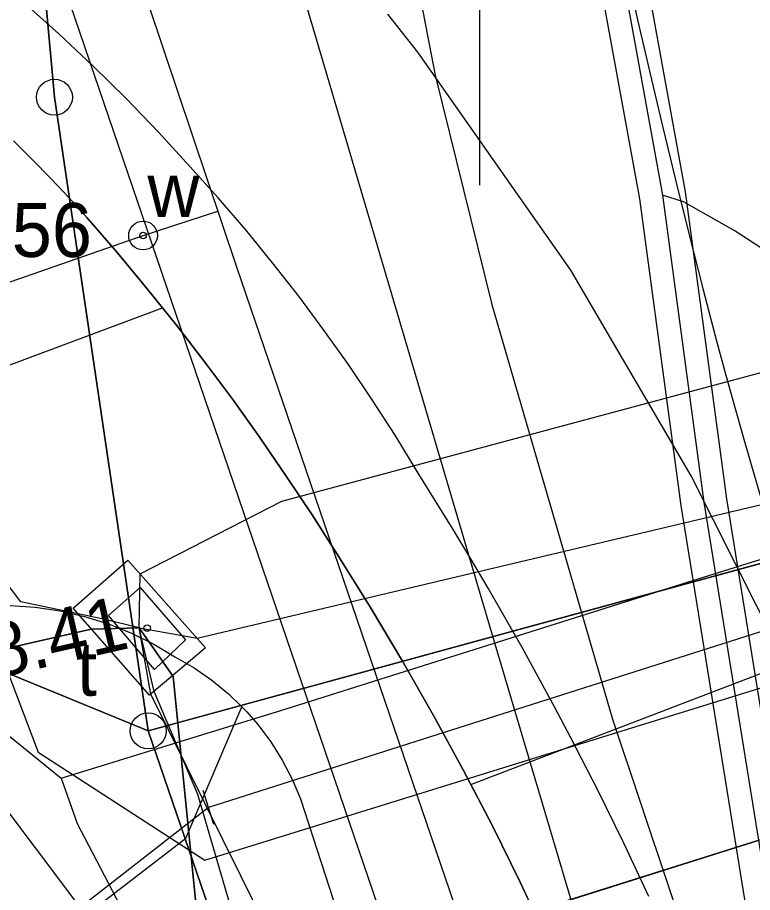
# Model space of a CAD drawing. Extents: x 6432121 to 6432331, y 5662538 to 5662686.
# Drawn here: x 6432243.57 to 6432253.79, y 5662637.67 to 5662649.83 of the extents above; entities that cross this region are included whole.
import ezdxf

# ---------------------------------------------------------------- set-up
doc = ezdxf.new("R2010")
doc.units = 0
for name, color, linetype in [('Warstwa 1', 7, 'Continuous'), ('Warstwa 10', 7, 'Continuous'), ('Warstwa 11', 7, 'Continuous'), ('Warstwa 12', 7, 'Continuous'), ('Warstwa 14', 7, 'Continuous'), ('Warstwa 15', 7, 'Continuous'), ('Warstwa 20', 7, 'Continuous'), ('Warstwa 37', 7, 'Continuous'), ('Warstwa 4', 7, 'Continuous'), ('Warstwa 5', 7, 'Continuous'), ('Warstwa 6', 7, 'Continuous'), ('Warstwa 61', 7, 'Continuous'), ('Warstwa 63', 7, 'Continuous'), ('Warstwa 8', 7, 'Continuous'), ('Warstwa 9', 7, 'Continuous')]:
    doc.layers.add(name, color=color, linetype=linetype)

msp = doc.modelspace()

# ---------------------------------------------------------------- linework, layer by layer
at = {"layer": 'Warstwa 1'}
for p, q in [((6432241.262, 5662679.658), (6432244.087, 5662648.722)), ((6432241.262, 5662679.658), (6432244.087, 5662648.722)), ((6432244.087, 5662648.722), (6432245.39, 5662639.916)), ((6432244.087, 5662648.722), (6432245.39, 5662639.916)), ((6432245.39, 5662639.916), (6432266.742, 5662645.747)), ((6432245.39, 5662639.916), (6432266.742, 5662645.747)), ((6432234.842, 5662644.244), (6432245.39, 5662639.916)), ((6432234.842, 5662644.244), (6432245.39, 5662639.916)), ((6432246.69, 5662636.13), (6432267.75, 5662642.76)), ((6432246.69, 5662636.13), (6432267.75, 5662642.76)), ((6432245.39, 5662639.916), (6432246.69, 5662636.13)), ((6432245.39, 5662639.916), (6432246.69, 5662636.13))]:
    msp.add_line(p, q, dxfattribs=at)
at = {"layer": 'Warstwa 10'}
for points in [[(6432272.61, 5662647.24), (6432246.23, 5662638.85)], [(6432246.23, 5662638.85), (6432244.48, 5662637.49), (6432244.8, 5662632.18)]]:
    msp.add_lwpolyline(points, dxfattribs=at)
for centre in [(6432244.087, 5662648.722), (6432245.39, 5662639.916)]:
    msp.add_circle(centre, 0.25, dxfattribs=at)
at = {"layer": 'Warstwa 11'}
msp.add_lwpolyline([(6432245.11, 5662642.29), (6432246.19, 5662641.07), (6432245.41, 5662640.41), (6432244.35, 5662641.62)], close=True, dxfattribs=at)
at = {"layer": 'Warstwa 12'}
for points in [[(6432260.149, 5662593.584), (6432259.505, 5662597.442), (6432258.113, 5662602.229), (6432246.261, 5662635.045), (6432242.6, 5662639.91), (6432237.105, 5662644.467), (6432235.235, 5662651.91), (6432228.3, 5662671.335), (6432227.148, 5662676.149), (6432227.614, 5662677.443), (6432228.191, 5662677.996), (6432231.551, 5662678.816), (6432233.235, 5662681.053)], [(6432245.267, 5662641.347), (6432245.28, 5662642.1), (6432247.25, 5662643.11), (6432265.86, 5662648.1), (6432266.37, 5662648.378), (6432266.59, 5662649.17), (6432271.25, 5662654.27), (6432275.48, 5662659.44), (6432277.44, 5662662.33), (6432277.171, 5662662.956), (6432277.15, 5662663.67), (6432276.74, 5662675.57), (6432276.54, 5662676.118), (6432276.69, 5662676.8), (6432276.108, 5662681.053)], [(6432245.267, 5662641.347), (6432245.28, 5662642.1), (6432247.25, 5662643.11), (6432265.86, 5662648.1), (6432266.37, 5662648.378), (6432266.59, 5662649.17), (6432271.25, 5662654.27), (6432275.48, 5662659.44), (6432277.44, 5662662.33), (6432277.171, 5662662.956), (6432276.74, 5662675.57), (6432276.54, 5662676.118), (6432276.69, 5662676.8), (6432276.108, 5662681.053)], [(6432251.161, 5662678.636), (6432251.195, 5662678.505), (6432250.722, 5662667.538), (6432250.449, 5662664.161), (6432250.95, 5662660.785), (6432251.946, 5662652.429), (6432252.859, 5662647.409), (6432253.435, 5662643.141), (6432255.033, 5662633.254), (6432255.483, 5662630.016), (6432258.492, 5662620.223), (6432259.57, 5662616.642), (6432259.85, 5662615.749), (6432260.538, 5662613.47), (6432262.28, 5662607.688), (6432262.524, 5662606.965), (6432264.736, 5662599.765)], [(6432264.124, 5662599.577), (6432261.914, 5662606.769), (6432261.67, 5662607.494), (6432259.926, 5662613.286), (6432259.238, 5662615.561), (6432258.958, 5662616.454), (6432257.88, 5662620.037), (6432254.857, 5662629.878), (6432254.401, 5662633.158), (6432252.801, 5662643.047), (6432252.227, 5662647.309), (6432251.312, 5662652.333), (6432250.316, 5662660.701), (6432249.805, 5662664.139), (6432250.084, 5662667.578), (6432250.551, 5662678.439), (6432250.541, 5662678.478)], [(6432244.451, 5662661.055), (6432244.51, 5662660.562), (6432244.747, 5662659.597), (6432247.148, 5662651.498), (6432250.159, 5662641.297), (6432254.564, 5662626.481), (6432257.548, 5662616.394), (6432260.807, 5662605.248), (6432262.453, 5662599.664), (6432266.272, 5662586.802), (6432268.265, 5662580.011), (6432268.423, 5662579.446)], [(6432243.958, 5662654.289), (6432246.621, 5662646.365), (6432250.032, 5662636.381), (6432251.998, 5662630.56), (6432253.864, 5662624.956), (6432256.122, 5662618.174), (6432258.071, 5662612.417), (6432261.076, 5662603.597), (6432261.907, 5662601.278), (6432263.382, 5662596.576), (6432264.52, 5662593.503), (6432265.328, 5662591.162), (6432268.156, 5662582.752), (6432268.733, 5662580.715)], [(6432243.16, 5662653.357), (6432252.465, 5662626.114), (6432254.893, 5662619.007), (6432257.883, 5662610.233), (6432261.03, 5662600.869), (6432263.754, 5662592.896), (6432267.107, 5662583.22), (6432267.857, 5662579.356), (6432269.061, 5662572.854)], [(6432246.73, 5662630.84), (6432246.66, 5662631.45), (6432245.74, 5662640.67), (6432245.267, 5662641.347), (6432244.6, 5662641.33), (6432196.62, 5662630.41), (6432162.36, 5662620.4), (6432161.76, 5662619.96), (6432161.08, 5662620.39), (6432144.64, 5662638.75), (6432139.05, 5662643.99), (6432134.66, 5662649.12), (6432133.76, 5662650.98), (6432133.196, 5662651.358)], [(6432245.267, 5662641.347), (6432244.77, 5662641.47), (6432244.417, 5662641.544), (6432243.62, 5662641.71), (6432240.1, 5662646.34), (6432237.97, 5662649.17), (6432237.33, 5662649.04), (6432237.05, 5662648.95)], [(6432178.74, 5662628.37), (6432200.37, 5662634.75), (6432206.97, 5662636.63), (6432221.29, 5662640.54), (6432232.17, 5662643.77), (6432238.49, 5662646.33), (6432240.86, 5662647.51), (6432243.86, 5662639.62), (6432246.18, 5662638.12), (6432265.49, 5662644.1), (6432264.97, 5662645.92)], [(6432261.405, 5662641.742), (6432260.919, 5662642.019), (6432257.433, 5662644.338), (6432253.539, 5662646.868), (6432252.834, 5662647.268), (6432252.543, 5662647.359)], [(6432157.15, 5662630.3), (6432157.97, 5662630.56), (6432158.44, 5662630.26), (6432165.06, 5662623.42), (6432193.45, 5662632.27), (6432200.21, 5662630.55), (6432202.99, 5662631.34), (6432212.51, 5662634.26), (6432214.29, 5662637.14), (6432238.97, 5662644.59), (6432245.32, 5662646.8), (6432246.36, 5662647.14)], [(6432272.61, 5662647.24), (6432246.23, 5662638.85)], [(6432245.267, 5662641.347), (6432246.071, 5662641.204), (6432265.703, 5662645.849)], [(6432244.181, 5662639.26), (6432247.309, 5662640.221), (6432252.89, 5662641.981), (6432259.86, 5662644.154), (6432263.572, 5662645.286)], [(6432233.564, 5662641.03), (6432237.009, 5662641.616), (6432240.509, 5662642.236), (6432244.181, 5662639.26)], [(6432161.76, 5662619.96), (6432162.36, 5662620.4), (6432196.62, 5662630.41), (6432244.6, 5662641.33), (6432245.267, 5662641.347)], [(6432245.267, 5662641.347), (6432245.74, 5662640.67), (6432246.66, 5662631.45), (6432246.75, 5662630.81)], [(6432248.82, 5662629.93), (6432248.531, 5662630.897), (6432248.931, 5662633.353), (6432245.428, 5662640.425), (6432245.267, 5662641.347)], [(6432248.82, 5662629.93), (6432248.84, 5662630.27), (6432247.19, 5662635.25), (6432246.08, 5662639.03), (6432245.474, 5662640.464), (6432245.267, 5662641.347)], [(6432244.181, 5662639.26), (6432244.403, 5662638.629), (6432246.131, 5662635.318), (6432247.214, 5662633.504), (6432248.295, 5662632.211), (6432249.036, 5662631.265), (6432249.61, 5662630.185)], [(6432246.23, 5662638.85), (6432244.48, 5662637.49), (6432244.8, 5662632.18)]]:
    msp.add_lwpolyline(points, dxfattribs=at)
at = {"layer": 'Warstwa 14'}
for centre in [(6432245.32, 5662646.8), (6432245.377, 5662641.344), (6432245.377, 5662641.343)]:
    msp.add_circle(centre, 0.045, dxfattribs=at)
at = {"layer": 'Warstwa 20'}
msp.add_line((6432246.306, 5662638.612), (6432246.154, 5662639.088), dxfattribs=at)
msp.add_line((6432246.306, 5662638.612), (6432246.154, 5662639.088), dxfattribs=at)
at = {"layer": 'Warstwa 37'}
for points in [[(6432252.027, 5662650.548), (6432252.197, 5662649.798), (6432252.37, 5662649.049), (6432252.548, 5662648.301), (6432252.73, 5662647.555), (6432252.916, 5662646.809), (6432253.106, 5662646.064), (6432253.3, 5662645.32), (6432253.426, 5662644.858), (6432253.554, 5662644.396), (6432253.685, 5662643.935), (6432253.817, 5662643.474), (6432253.952, 5662643.014), (6432254.088, 5662642.555), (6432254.227, 5662642.096), (6432254.367, 5662641.638), (6432254.51, 5662641.18), (6432256.27, 5662635.89), (6432257.45, 5662632.38), (6432259.09, 5662627.49)], [(6432249.116, 5662650.415), (6432249.248, 5662649.722), (6432249.38, 5662649.03), (6432250.17, 5662645.84), (6432251.85, 5662640.08), (6432254.2, 5662633.06), (6432255.4, 5662629.47), (6432256.37, 5662626.58)], [(6432252.354, 5662637.614), (6432252.005, 5662638.355), (6432251.643, 5662639.091), (6432251.27, 5662639.82), (6432251.047, 5662640.239), (6432250.82, 5662640.657), (6432250.59, 5662641.072), (6432250.356, 5662641.486), (6432250.118, 5662641.897), (6432249.876, 5662642.306), (6432249.631, 5662642.713), (6432249.382, 5662643.118), (6432249.13, 5662643.52), (6432248.824, 5662644.023), (6432248.506, 5662644.518), (6432248.176, 5662645.006), (6432247.836, 5662645.486), (6432247.484, 5662645.958), (6432247.121, 5662646.421), (6432246.748, 5662646.877), (6432246.364, 5662647.323), (6432245.97, 5662647.76), (6432245.533, 5662648.238), (6432245.085, 5662648.705), (6432244.623, 5662649.16), (6432244.15, 5662649.603), (6432243.666, 5662650.033)], [(6432256.27, 5662635.89), (6432256.075, 5662636.478), (6432255.87, 5662637.062), (6432255.655, 5662637.642), (6432255.43, 5662638.219), (6432255.196, 5662638.792), (6432254.951, 5662639.36), (6432254.697, 5662639.925), (6432254.433, 5662640.485), (6432254.16, 5662641.04), (6432252.94, 5662643.46), (6432251.27, 5662646.32), (6432249.14, 5662649.35), (6432248.723, 5662649.876)]]:
    msp.add_lwpolyline(points, dxfattribs=at)
at = {"layer": 'Warstwa 4'}
msp.add_lwpolyline([(6432244.84, 5662641.52), (6432245.28, 5662641.91), (6432245.91, 5662641.18), (6432245.48, 5662640.77)], close=True, dxfattribs=at)
msp.add_circle((6432245.32, 5662646.8), 0.2, dxfattribs=at)
at = {"layer": 'Warstwa 5'}
for p, q in [((6432243.474, 5662641.656), (6432243.821, 5662641.633)), ((6432243.821, 5662641.633), (6432244.166, 5662641.583)), ((6432244.166, 5662641.583), (6432244.505, 5662641.506)), ((6432244.505, 5662641.506), (6432244.837, 5662641.402)), ((6432244.837, 5662641.402), (6432245.16, 5662641.273)), ((6432245.16, 5662641.273), (6432245.471, 5662641.119)), ((6432245.471, 5662641.119), (6432245.77, 5662640.94)), ((6432245.77, 5662640.94), (6432246.029, 5662640.791)), ((6432246.029, 5662640.791), (6432246.274, 5662640.621)), ((6432246.274, 5662640.621), (6432246.506, 5662640.432)), ((6432246.506, 5662640.432), (6432246.694, 5662640.251)), ((6432246.173, 5662639.029), (6432246.694, 5662640.251)), ((6432245.914, 5662638.423), (6432246.173, 5662639.029)), ((6432241.65, 5662635.152), (6432245.914, 5662638.423))]:
    msp.add_line(p, q, dxfattribs=at)
at = {"layer": 'Warstwa 6'}
for points in [[(6432241.262, 5662681.053), (6432241.262, 5662679.658), (6432244.087, 5662648.722), (6432245.39, 5662639.916), (6432266.742, 5662645.747), (6432263.798, 5662654.493), (6432266.973, 5662662.325), (6432263.799, 5662681.053)], [(6432253.68, 5662630.32), (6432251.63, 5662635.43), (6432251.29, 5662636.231), (6432250.934, 5662637.026), (6432250.563, 5662637.813), (6432250.177, 5662638.593), (6432249.775, 5662639.365), (6432249.359, 5662640.129), (6432248.927, 5662640.885), (6432248.481, 5662641.632), (6432248.02, 5662642.37), (6432247.671, 5662642.917), (6432247.312, 5662643.457), (6432246.944, 5662643.991), (6432246.566, 5662644.519), (6432246.179, 5662645.039), (6432245.783, 5662645.553), (6432245.377, 5662646.059), (6432244.963, 5662646.558), (6432244.54, 5662647.05), (6432244.291, 5662647.324), (6432244.038, 5662647.593), (6432243.779, 5662647.857), (6432243.516, 5662648.117)], [(6432295.199, 5662556.053), (6432289.811, 5662577.223), (6432287.64, 5662583.69), (6432267.75, 5662642.76), (6432246.69, 5662636.13), (6432263.163, 5662588.197), (6432269.007, 5662560.534), (6432269.756, 5662556.053)]]:
    msp.add_lwpolyline(points, dxfattribs=at)
for points in [[(6432234.842, 5662644.244), (6432245.39, 5662639.916), (6432244.087, 5662648.722), (6432241.262, 5662679.658), (6432232.544, 5662677.413), (6432183.398, 5662664.76), (6432164.325, 5662660.371), (6432136.954, 5662653.004), (6432141.907, 5662600.47), (6432147.05, 5662605.45), (6432164.332, 5662622.19), (6432166.394, 5662623.975)], [(6432245.39, 5662639.916), (6432246.69, 5662636.13), (6432267.75, 5662642.76), (6432266.742, 5662645.747)], [(6432166.394, 5662623.975), (6432164.332, 5662622.19), (6432180.9, 5662615.82), (6432193.86, 5662619.79), (6432228.29, 5662630.34), (6432246.69, 5662636.13), (6432245.39, 5662639.916), (6432234.842, 5662644.244)]]:
    msp.add_lwpolyline(points, close=True, dxfattribs=at)
at = {"layer": 'Warstwa 61'}
msp.add_lwpolyline([(6432250.819, 5662681.053), (6432250.821, 5662679.711), (6432250.716, 5662679.086), (6432250.873, 5662678.472), (6432250.403, 5662667.558), (6432250.127, 5662664.15), (6432250.633, 5662660.743), (6432251.629, 5662652.381), (6432252.543, 5662647.359), (6432253.118, 5662643.094), (6432254.717, 5662633.206), (6432255.17, 5662629.947), (6432255.2, 5662629.93), (6432258.186, 5662620.13), (6432259.264, 5662616.548), (6432259.544, 5662615.655), (6432260.232, 5662613.378), (6432261.975, 5662607.591), (6432262.219, 5662606.867), (6432264.43, 5662599.671)], dxfattribs=at)
at = {"layer": 'Warstwa 63'}
msp.add_line((6432250, 5662652.5), (6432250, 5662647.5), dxfattribs=at)
at = {"layer": 'Warstwa 8'}
for p, q in [((6432243.516, 5662648.117), (6432243.779, 5662647.857)), ((6432243.779, 5662647.857), (6432244.038, 5662647.593)), ((6432244.038, 5662647.593), (6432244.291, 5662647.324)), ((6432244.291, 5662647.324), (6432244.54, 5662647.05)), ((6432244.54, 5662647.05), (6432244.963, 5662646.558)), ((6432244.963, 5662646.558), (6432245.377, 5662646.059)), ((6432245.377, 5662646.059), (6432245.588, 5662645.796)), ((6432245.588, 5662645.796), (6432245.783, 5662645.553)), ((6432245.783, 5662645.553), (6432246.179, 5662645.039)), ((6432246.179, 5662645.039), (6432246.566, 5662644.519)), ((6432246.566, 5662644.519), (6432246.944, 5662643.991)), ((6432246.944, 5662643.991), (6432247.312, 5662643.457)), ((6432247.312, 5662643.457), (6432247.671, 5662642.917)), ((6432247.671, 5662642.917), (6432248.02, 5662642.37)), ((6432248.02, 5662642.37), (6432248.481, 5662641.632)), ((6432248.481, 5662641.632), (6432248.927, 5662640.885)), ((6432249.876, 5662639.171), (6432255.26, 5662641.23)), ((6432249.876, 5662639.171), (6432255.26, 5662641.23)), ((6432248.927, 5662640.885), (6432249.359, 5662640.129)), ((6432249.359, 5662640.129), (6432249.775, 5662639.365)), ((6432249.775, 5662639.365), (6432249.876, 5662639.171)), ((6432249.876, 5662639.171), (6432250.177, 5662638.593)), ((6432250.177, 5662638.593), (6432250.563, 5662637.813)), ((6432250.563, 5662637.813), (6432250.934, 5662637.026))]:
    msp.add_line(p, q, dxfattribs=at)
for points in [[(6432245.28, 5662642.1), (6432247.25, 5662643.11), (6432265.86, 5662648.1)], [(6432246.18, 5662638.12), (6432265.49, 5662644.1)]]:
    msp.add_lwpolyline(points, dxfattribs=at)
at = {"layer": 'Warstwa 9'}
for p, q in [((6432243.516, 5662648.117), (6432243.779, 5662647.857)), ((6432243.779, 5662647.857), (6432244.038, 5662647.593)), ((6432244.038, 5662647.593), (6432244.291, 5662647.324)), ((6432244.291, 5662647.324), (6432244.54, 5662647.05)), ((6432244.54, 5662647.05), (6432244.963, 5662646.558)), ((6432244.963, 5662646.558), (6432245.377, 5662646.059)), ((6432245.377, 5662646.059), (6432245.588, 5662645.796)), ((6432235.12, 5662641.89), (6432245.588, 5662645.796)), ((6432235.12, 5662641.89), (6432245.588, 5662645.796)), ((6432245.588, 5662645.796), (6432245.783, 5662645.553)), ((6432245.783, 5662645.553), (6432246.179, 5662645.039)), ((6432246.179, 5662645.039), (6432246.566, 5662644.519)), ((6432246.566, 5662644.519), (6432246.944, 5662643.991)), ((6432246.944, 5662643.991), (6432247.312, 5662643.457)), ((6432247.312, 5662643.457), (6432247.671, 5662642.917)), ((6432247.671, 5662642.917), (6432248.02, 5662642.37)), ((6432248.02, 5662642.37), (6432248.481, 5662641.632)), ((6432243.474, 5662641.656), (6432243.821, 5662641.633)), ((6432243.821, 5662641.633), (6432244.166, 5662641.583)), ((6432244.166, 5662641.583), (6432244.505, 5662641.506)), ((6432248.481, 5662641.632), (6432248.927, 5662640.885)), ((6432244.505, 5662641.506), (6432244.837, 5662641.402)), ((6432244.837, 5662641.402), (6432245.16, 5662641.273)), ((6432245.16, 5662641.273), (6432245.471, 5662641.119)), ((6432245.471, 5662641.119), (6432245.77, 5662640.94)), ((6432245.77, 5662640.94), (6432246.029, 5662640.791)), ((6432248.927, 5662640.885), (6432249.359, 5662640.129)), ((6432246.029, 5662640.791), (6432246.274, 5662640.621)), ((6432246.274, 5662640.621), (6432246.506, 5662640.432)), ((6432246.506, 5662640.432), (6432246.694, 5662640.251)), ((6432246.173, 5662639.029), (6432246.694, 5662640.251)), ((6432246.694, 5662640.251), (6432246.762, 5662640.179)), ((6432246.694, 5662640.251), (6432246.762, 5662640.179)), ((6432246.762, 5662640.179), (6432246.918, 5662640.002)), ((6432246.762, 5662640.179), (6432246.918, 5662640.002)), ((6432249.359, 5662640.129), (6432249.775, 5662639.365)), ((6432246.918, 5662640.002), (6432247.097, 5662639.763)), ((6432246.918, 5662640.002), (6432247.097, 5662639.763)), ((6432247.097, 5662639.763), (6432247.256, 5662639.51)), ((6432247.097, 5662639.763), (6432247.256, 5662639.51)), ((6432247.256, 5662639.51), (6432247.394, 5662639.245)), ((6432247.256, 5662639.51), (6432247.394, 5662639.245)), ((6432249.775, 5662639.365), (6432250.177, 5662638.593)), ((6432247.394, 5662639.245), (6432247.51, 5662638.97)), ((6432247.394, 5662639.245), (6432247.51, 5662638.97)), ((6432245.914, 5662638.423), (6432246.173, 5662639.029)), ((6432247.51, 5662638.97), (6432250.664, 5662629.247)), ((6432247.51, 5662638.97), (6432248.604, 5662635.596)), ((6432250.177, 5662638.593), (6432250.563, 5662637.813)), ((6432241.65, 5662635.152), (6432245.914, 5662638.423)), ((6432250.563, 5662637.813), (6432250.934, 5662637.026))]:
    msp.add_line(p, q, dxfattribs=at)

# ---------------------------------------------------------------- texts
at = {"layer": 'Warstwa 14'}
msp.add_text('118.41', height=0.75, rotation=12.8228, dxfattribs=at).set_placement((6432242.163, 5662640.39))
at = {"layer": 'Warstwa 15'}
msp.add_text('119.56', height=0.75, dxfattribs=at).set_placement((6432241.542, 5662646.502))
at = {"layer": 'Warstwa 5'}
for s, p in [('w', (6432245.381, 5662647.056)), ('t', (6432244.401, 5662640.404))]:
    msp.add_text(s, height=0.75, dxfattribs=at).set_placement(p)

doc.saveas('drawing.dxf')
